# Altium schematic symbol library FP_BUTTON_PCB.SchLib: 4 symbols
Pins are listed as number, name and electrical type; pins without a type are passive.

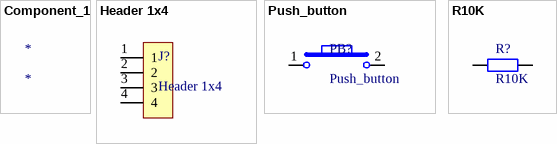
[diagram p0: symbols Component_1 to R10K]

## Component_1
designator *

## Header 1x4
designator J?
footprint HDR4X1_FEMALE
pins: 1, 2, 3, 4

## Push_button
designator PB?
PTS636SM25FSMTR LFS
footprint button_12x12
pins: 1, 2

## R10K
designator R?
footprint RES1206
pins: 1, 2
